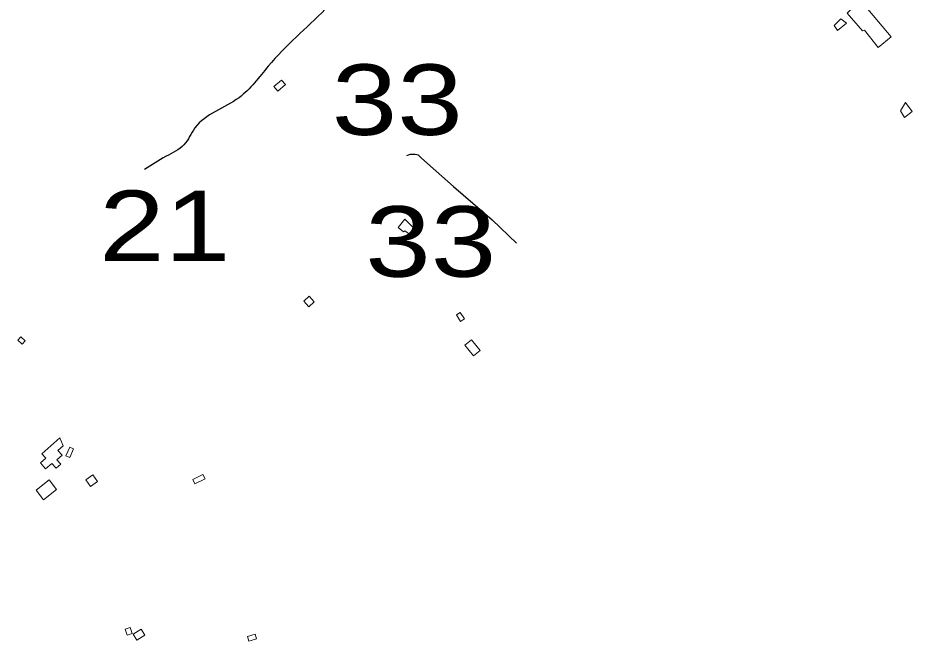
# Model space of a CAD drawing. Extents: x 476989 to 498418, y 4381813 to 4416555.
# Drawn here: x 485656 to 486290, y 4385438 to 4385880 of the extents above; entities that cross this region are included whole.
import ezdxf
from ezdxf.enums import TextEntityAlignment as Align

# ---------------------------------------------------------------- set-up
doc = ezdxf.new("R2010")
doc.units = 0
doc.header["$LTSCALE"] = 20
for name, color, linetype, lineweight in [('13', 7, 'Continuous', 13), ('47', 7, 'Continuous', 13), ('6', 7, 'Continuous', 25)]:
    doc.layers.add(name, color=color, linetype=linetype, lineweight=lineweight)

msp = doc.modelspace()

# ---------------------------------------------------------------- linework, layer by layer
at = {"layer": '47'}
for points in [[(486275.73, 4385866.54), (486253.81, 4385892.3), (486244.45, 4385883.13), (486255.23, 4385870.81), (486256.66, 4385871.24), (486266.32, 4385858.95)], [(486239.89, 4385879.21), (486235.17, 4385874.48), (486237.52, 4385870.92), (486244.05, 4385876.23)], [(485843.31, 4385835.83), (485846.04, 4385832.55), (485840.57, 4385827.99), (485837.84, 4385831.27)], [(486290.5, 4385813.58), (486285.12, 4385809.31), (486282.25, 4385813.92), (486285.87, 4385819.8)], [(485930.74, 4385737.25), (485937.99, 4385729.79), (485934.78, 4385726.16), (485930.62, 4385729), (485929.71, 4385728.11), (485925.93, 4385731.31)], [(485862.8, 4385682.54), (485859.04, 4385679.07), (485862.69, 4385675.12), (485866.45, 4385678.59)], [(485967.28, 4385669.27), (485970.22, 4385664.72), (485972.94, 4385666.48), (485970, 4385671.03)], [(485658.29, 4385653.66), (485661.38, 4385650.92), (485659.34, 4385648.62), (485656.25, 4385651.36)], [(485973.2, 4385647.8), (485979.51, 4385640.27), (485984.18, 4385644.19), (485977.87, 4385651.72)], [(485686, 4385582.05), (485673.31, 4385570.9), (485676.11, 4385567.69), (485672.26, 4385564.34), (485675.87, 4385560.17), (485680.34, 4385564.05), (485683.31, 4385560.61), (485686.6, 4385563.46), (485683.93, 4385566.52), (485687.71, 4385569.83), (485684.68, 4385573.28), (485688.41, 4385576.56)], [(485693.04, 4385575.65), (485690.28, 4385569.34), (485693, 4385568.15), (485695.76, 4385574.46)], [(485709.41, 4385555.83), (485704.45, 4385552.39), (485707.72, 4385547.67), (485712.68, 4385551.11)], [(485787.53, 4385556.14), (485780.27, 4385552.57), (485781.8, 4385549.46), (485789.06, 4385553.03)], [(485683.68, 4385545.62), (485674.4, 4385538.3), (485669.11, 4385545), (485678.39, 4385552.32)], [(485736, 4385447.7), (485737.37, 4385443.37), (485733.82, 4385442.25), (485732.45, 4385446.58)], [(485743.71, 4385446.46), (485738.03, 4385443.02), (485740.6, 4385438.78), (485746.28, 4385442.22)], [(485819.05, 4385441.33), (485824.55, 4385443.01), (485825.55, 4385439.73), (485820.05, 4385438.05)]]:
    msp.add_lwpolyline(points, close=True, dxfattribs=at)
at = {"layer": '6'}
msp.add_lwpolyline([(485932.11, 4385782.21), (485933.32, 4385782.91), (485934.79, 4385783.22), (485937.94, 4385783.17), (485939.15, 4385783.07), (485940.12, 4385782.7), (485942.48, 4385780.51), (485965.14, 4385760.38), (485992.65, 4385736.64), (486009.82, 4385720.15)], dxfattribs=at)
msp.add_spline([(485956.23, 4385971.26), (485947.54, 4385961.52), (485930.31, 4385942.56), (485916.08, 4385928.8), (485905.26, 4385917.55), (485892.78, 4385905.28), (485874.27, 4385886.03), (485833.81, 4385845.65), (485813.14, 4385823.32), (485781.72, 4385801.83), (485774.07, 4385789.96), (485761.33, 4385781.76), (485746.04, 4385772.43)], degree=3, dxfattribs=at)

# ---------------------------------------------------------------- texts
at = {"layer": '13', "width": 1.25}
for s, p in [('33', (485925.31, 4385796.92)), ('21', (485760.4, 4385707.46)), ('33', (485949.08, 4385696.37))]:
    msp.add_text(s, height=50, dxfattribs=at).set_placement(p, align=Align.CENTER)

doc.saveas('drawing.dxf')
